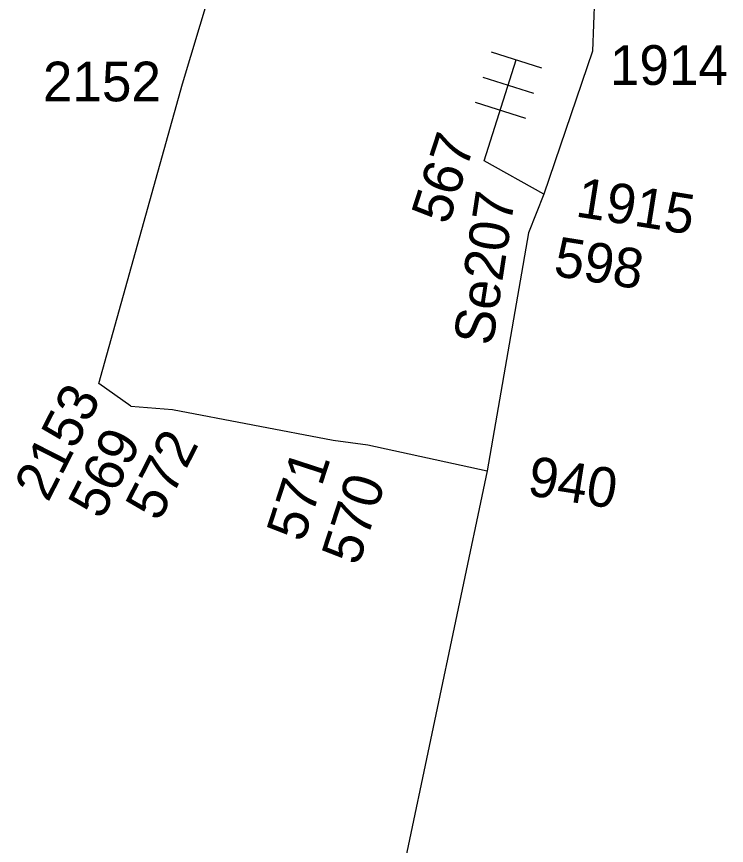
# Model space of a CAD drawing. Extents: x -535557 to -534097, y -1142175 to -1136716.
# Drawn here: x -534449.24 to -534435.82, y -1139849.61 to -1139833.95 of the extents above; entities that cross this region are included whole.
import ezdxf

# ---------------------------------------------------------------- set-up
doc = ezdxf.new("R2010")
doc.units = 0
doc.layers.add('Default', color=7, linetype='Continuous')
doc.layers.add('SS_SZDC', color=7, linetype='Continuous')

# ---------------------------------------------------------------- blocks, each defined once
blk = doc.blocks.new('POINT_DISPLAY')
at = {"layer": 'Default'}
blk.add_line((0, 0), (0, 0), dxfattribs=at)

msp = doc.modelspace()

# ---------------------------------------------------------------- linework, layer by layer
at = {"layer": 'SS_SZDC'}
for p, q in [((-534446.1, -1139835.219), (-534445.069, -1139831.78)), ((-534438.26, -1139832.09), (-534438.35, -1139834.6)), ((-534440.27, -1139834.612), (-534439.317, -1139834.915)), ((-534438.35, -1139834.6), (-534439.27, -1139837.299)), ((-534440.399, -1139836.67), (-534439.794, -1139834.763)), ((-534440.422, -1139835.089), (-534439.469, -1139835.391)), ((-534447.68, -1139840.879), (-534446.1, -1139835.219)), ((-534440.573, -1139835.565), (-534439.62, -1139835.868)), ((-534439.27, -1139837.299), (-534440.399, -1139836.67)), ((-534439.27, -1139837.299), (-534439.56, -1139838.03)), ((-534439.56, -1139838.03), (-534440.34, -1139842.53)), ((-534447.079, -1139841.309), (-534447.68, -1139840.879)), ((-534447.079, -1139841.309), (-534446.289, -1139841.37)), ((-534446.289, -1139841.37), (-534443.25, -1139841.95)), ((-534443.25, -1139841.95), (-534442.6, -1139842.04)), ((-534442.6, -1139842.04), (-534440.34, -1139842.53)), ((-534440.34, -1139842.53), (-534443.609, -1139857.989))]:
    msp.add_line(p, q, dxfattribs=at)

# ---------------------------------------------------------------- block references
for p in [(-534438.35, -1139834.6), (-534446.1, -1139835.219), (-534440.399, -1139836.67), (-534439.27, -1139837.299), (-534439.56, -1139838.03), (-534447.68, -1139840.879), (-534447.079, -1139841.309), (-534446.289, -1139841.37), (-534443.25, -1139841.95), (-534442.6, -1139842.04), (-534440.34, -1139842.53)]:
    msp.add_blockref('POINT_DISPLAY', p, dxfattribs=at)

# ---------------------------------------------------------------- texts
for s, p in [('1914', (-534438.024, -1139835.236)), ('2152', (-534448.738, -1139835.547))]:
    msp.add_text(s, height=0.75, dxfattribs=at).set_placement(p)
for s, rotation, p in [('567', 72, (-534441.08, -1139837.901)), ('1915', 351, (-534438.692, -1139837.72)), ('Se207', 81.3757, (-534440.243, -1139840.184)), ('598', 351, (-534439.109, -1139838.841)), ('2153', 63, (-534448.641, -1139843.142)), ('569', 63, (-534447.625, -1139843.474)), ('572', 63, (-534446.542, -1139843.512)), ('571', 72, (-534443.817, -1139843.902)), ('940', 351, (-534439.606, -1139842.987)), ('570', 72, (-534442.777, -1139844.343))]:
    msp.add_text(s, height=0.75, rotation=rotation, dxfattribs=at).set_placement(p)

doc.saveas('drawing.dxf')
